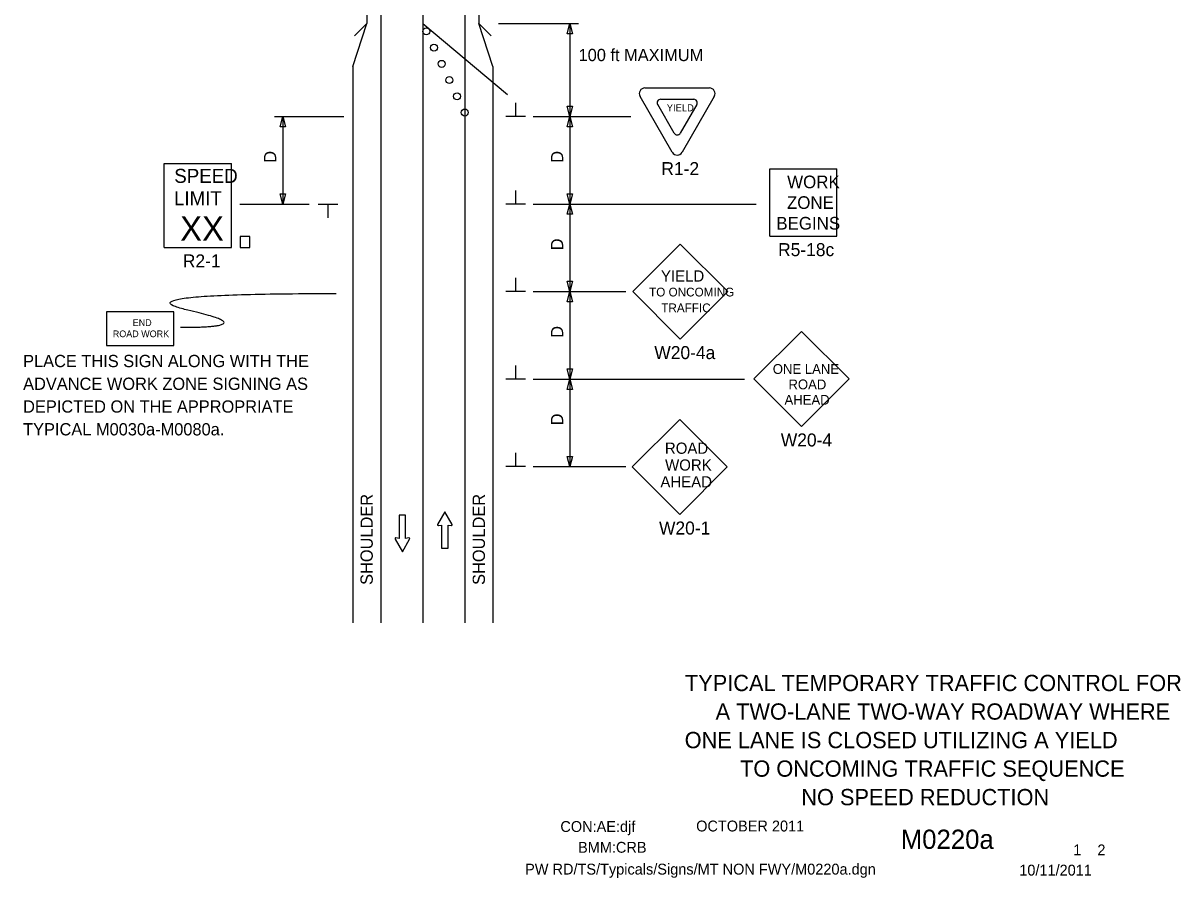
# Model space of a CAD drawing. Extents: x 16784 to 18475, y 7218 to 8259.
# Drawn here: x 16784 to 17445, y 7218 to 7706 of the extents above; entities that cross this region are included whole.
import ezdxf

# ---------------------------------------------------------------- set-up
doc = ezdxf.new("R2010")
doc.units = 0
for name, color, linetype in [('BORDER', 7, 'Continuous'), ('BORDER_SIGNAL_WO', 7, 'Continuous'), ('MT_SCRATCH_LEVEL_E', 7, 'Continuous'), ('PAVT_EDGE_EX', 7, 'Continuous'), ('TRAFFIC_SIGNS_PR', 7, 'Continuous'), ('TYPICAL_TEXT_DIMEN_PR', 7, 'Continuous')]:
    doc.layers.add(name, color=color, linetype=linetype)

msp = doc.modelspace()

# ---------------------------------------------------------------- linework, layer by layer
at = {"layer": 'MT_SCRATCH_LEVEL_E'}
for p, q in [((17002.27, 7425.26), (16998.52, 7425.26)), ((16998.52, 7425.26), (16998.52, 7412.01)), ((17002.27, 7425.26), (16998.52, 7425.26)), ((16998.52, 7425.26), (16998.52, 7412.01)), ((17002.27, 7412.01), (17002.27, 7425.26)), ((17002.27, 7412.01), (17002.27, 7425.26)), ((17024.66, 7427.22), (17020.55, 7419.98)), ((17024.66, 7427.22), (17020.55, 7419.98)), ((17028.81, 7419.98), (17024.66, 7427.22)), ((17028.81, 7419.98), (17024.66, 7427.22)), ((17021.03, 7419.29), (17022.81, 7419.61)), ((17021.03, 7419.29), (17022.81, 7419.61)), ((17022.81, 7419.61), (17022.81, 7406.35)), ((17022.81, 7419.61), (17022.81, 7406.35)), ((17026.55, 7406.35), (17026.55, 7419.61)), ((17026.55, 7419.61), (17028.33, 7419.29)), ((17026.55, 7406.35), (17026.55, 7419.61)), ((17026.55, 7419.61), (17028.33, 7419.29)), ((16996.27, 7411.64), (17000.41, 7404.4)), ((16996.27, 7411.64), (17000.41, 7404.4)), ((16998.52, 7412.01), (16996.75, 7412.32)), ((16998.52, 7412.01), (16996.75, 7412.32)), ((17000.41, 7404.4), (17004.53, 7411.64)), ((17000.41, 7404.4), (17004.53, 7411.64)), ((17004.04, 7412.32), (17002.27, 7412.01)), ((17004.04, 7412.32), (17002.27, 7412.01)), ((17022.81, 7406.35), (17026.55, 7406.35)), ((17022.81, 7406.35), (17026.55, 7406.35))]:
    msp.add_line(p, q, dxfattribs=at)
for centre, start, end in [((17020.95, 7419.75), 150.42484, 279.96381), ((17020.95, 7419.75), 150.42484, 279.96381), ((17028.4, 7419.75), 260.03619, 29.77312), ((17028.4, 7419.75), 260.03619, 29.77312), ((16996.68, 7411.86), 80.03619, 209.77312), ((16996.68, 7411.86), 80.03619, 209.77312), ((17004.12, 7411.86), 330.42484, 99.96381), ((17004.12, 7411.86), 330.42484, 99.96381)]:
    msp.add_arc(centre, 0.463, start, end, dxfattribs=at)
at = {"layer": 'PAVT_EDGE_EX'}
for p, q in [((16988.07, 8185.68), (16988.07, 7363.75)), ((17012.07, 8185.68), (17012.07, 7363.75)), ((17036.07, 8185.68), (17036.07, 7363.75)), ((16980.07, 7837.6), (16980.07, 7706.21)), ((17012.07, 7837.6), (17012.07, 7706.21)), ((17044.07, 7837.6), (17044.07, 7706.21)), ((16972.07, 7681.51), (16980.07, 7706.21)), ((16980.07, 7706.21), (16973, 7699.14)), ((17012.07, 7706.21), (17060.48, 7665.59)), ((17044.07, 7706.21), (17051.14, 7699.14)), ((17052.07, 7681.51), (17044.07, 7706.21)), ((16972.07, 7681.51), (16972.07, 7363.75)), ((17052.07, 7681.51), (17052.07, 7363.75))]:
    msp.add_line(p, q, dxfattribs=at)
for points in [[(17012.07, 7685.68), (17012.07, 7660.68)], [(17012.07, 7585.68), (17012.07, 7560.68)], [(17012.07, 7485.68), (17012.07, 7460.68)], [(17012.07, 7385.68), (17012.07, 7363.75)]]:
    msp.add_lwpolyline(points, dxfattribs=at)
at = {"layer": 'TRAFFIC_SIGNS_PR'}
for p, q in [((17138.98, 7669.34), (17175.9, 7669.34)), ((17154.67, 7632.57), (17136.21, 7664.54)), ((17148.03, 7662.87), (17166.93, 7662.87)), ((17178.67, 7664.54), (17160.21, 7632.57)), ((17155.75, 7643.5), (17146.3, 7659.87)), ((17168.66, 7659.87), (17159.21, 7643.5)), ((16864.3, 7626.26), (16902.7, 7626.26)), ((16864.3, 7578.26), (16864.3, 7626.26)), ((16902.7, 7578.26), (16902.7, 7626.26)), ((17210.31, 7584.69), (17210.31, 7623.09)), ((17210.31, 7623.09), (17248.71, 7623.09)), ((17248.71, 7584.69), (17248.71, 7623.09)), ((17210.31, 7584.69), (17248.71, 7584.69)), ((16864.3, 7578.26), (16902.7, 7578.26)), ((17159.25, 7580.19), (17132.09, 7553.04)), ((17186.4, 7553.04), (17159.25, 7580.19)), ((17132.09, 7553.04), (17159.25, 7525.88)), ((17159.25, 7525.88), (17186.4, 7553.04)), ((17228.49, 7530.26), (17201.34, 7503.11)), ((17255.64, 7503.11), (17228.49, 7530.26)), ((17201.34, 7503.11), (17228.49, 7475.96)), ((17228.49, 7475.96), (17255.64, 7503.11)), ((17158.9, 7479.95), (17131.74, 7452.8)), ((17186.05, 7452.8), (17158.9, 7479.95)), ((17131.74, 7452.8), (17158.9, 7425.65)), ((17158.9, 7425.65), (17186.05, 7452.8))]:
    msp.add_line(p, q, dxfattribs=at)
for points in [[(16907.71, 7578.26), (16913.31, 7578.26), (16913.31, 7584.43), (16907.71, 7584.43)], [(16831.33, 7522.23), (16869.73, 7522.23), (16869.73, 7541.43), (16831.33, 7541.43)]]:
    msp.add_lwpolyline(points, close=True, dxfattribs=at)
for centre in [(17014.07, 7701.63), (17018.47, 7692.37), (17022.87, 7683.1), (17027.27, 7673.84), (17031.67, 7664.57), (17036.07, 7655.31)]:
    msp.add_circle(centre, 2, dxfattribs=at)
for centre, radius, start, end in [((17138.98, 7666.14), 3.2, 90, 209.99924), ((17175.9, 7666.14), 3.2, 330.11476, 90), ((17133.44, 7662.94), 3.2, 29.99562, 29.99924), ((17148.03, 7660.87), 2, 90, 210.00073), ((17166.93, 7660.87), 2, 329.99927, 90), ((17157.48, 7644.5), 2, 210.00073, 329.99927), ((17157.44, 7634.17), 3.2, 209.99562, 211.51401), ((17157.44, 7634.17), 3.2, 211.51401, 330.00085), ((17162.98, 7630.97), 3.2, 149.99998, 150.00086)]:
    msp.add_arc(centre, radius, start, end, dxfattribs=at)
msp.add_open_spline([(16873.64, 7532.59), (16920.88, 7532.59), (16835.86, 7551.93), (16962.53, 7551.93)], degree=2, dxfattribs=at)
at = {"layer": 'TYPICAL_TEXT_DIMEN_PR'}
for p, q in [((17055.37, 7706.21), (17101.07, 7706.21)), ((17094.5, 7700.35), (17096.07, 7706.21)), ((17096.07, 7706.21), (17096.07, 7653.01)), ((17096.07, 7706.21), (17097.64, 7700.35)), ((17096.07, 7700.35), (17094.5, 7700.35)), ((17097.64, 7700.35), (17096.07, 7700.35)), ((17065.19, 7653.01), (17065.19, 7660.8)), ((17096.07, 7653.01), (17094.5, 7658.88)), ((17094.5, 7658.88), (17096.07, 7658.88)), ((17096.07, 7658.88), (17097.64, 7658.88)), ((17097.64, 7658.88), (17096.07, 7653.01)), ((16927.3, 7653.01), (16967.03, 7653.01)), ((16930.5, 7647.15), (16932.07, 7653.01)), ((16932.07, 7653.01), (16932.07, 7603.01)), ((16932.07, 7653.01), (16933.64, 7647.15)), ((17070.82, 7653.01), (17059.57, 7653.01)), ((17075.07, 7653.01), (17131.03, 7653.01)), ((17094.5, 7647.15), (17096.07, 7653.01)), ((17096.07, 7653.01), (17096.07, 7603.01)), ((17096.07, 7653.01), (17097.64, 7647.15)), ((16932.07, 7647.15), (16930.5, 7647.15)), ((16933.64, 7647.15), (16932.07, 7647.15)), ((17096.07, 7647.15), (17094.5, 7647.15)), ((17097.64, 7647.15), (17096.07, 7647.15)), ((16932.07, 7603.01), (16930.5, 7608.88)), ((16930.5, 7608.88), (16932.07, 7608.88)), ((16932.07, 7608.88), (16933.64, 7608.88)), ((16933.64, 7608.88), (16932.07, 7603.01)), ((17065.19, 7603.01), (17065.19, 7610.8)), ((17096.07, 7603.01), (17094.5, 7608.88)), ((17094.5, 7608.88), (17096.07, 7608.88)), ((17096.07, 7608.88), (17097.64, 7608.88)), ((17097.64, 7608.88), (17096.07, 7603.01)), ((16907.47, 7603.01), (16947.14, 7603.01)), ((16952.2, 7603.01), (16963.45, 7603.01)), ((16957.82, 7603.01), (16957.82, 7595.23)), ((17070.82, 7603.01), (17059.57, 7603.01)), ((17075.07, 7603.01), (17202.6, 7603.01)), ((17094.5, 7597.15), (17096.07, 7603.01)), ((17094.5, 7597.15), (17096.07, 7603.01)), ((17096.07, 7603.01), (17096.07, 7553.01)), ((17096.07, 7603.01), (17097.64, 7597.15)), ((17096.07, 7603.01), (17097.64, 7597.15)), ((17096.07, 7597.15), (17094.5, 7597.15)), ((17096.07, 7597.15), (17094.5, 7597.15)), ((17097.64, 7597.15), (17096.07, 7597.15)), ((17097.64, 7597.15), (17096.07, 7597.15)), ((17065.19, 7553.01), (17065.19, 7560.8)), ((17096.07, 7553.01), (17094.5, 7558.88)), ((17094.5, 7558.88), (17096.07, 7558.88)), ((17096.07, 7553.01), (17094.5, 7558.88)), ((17094.5, 7558.88), (17096.07, 7558.88)), ((17096.07, 7558.88), (17097.64, 7558.88)), ((17097.64, 7558.88), (17096.07, 7553.01)), ((17096.07, 7558.88), (17097.64, 7558.88)), ((17097.64, 7558.88), (17096.07, 7553.01)), ((17070.82, 7553.01), (17059.57, 7553.01)), ((17075.07, 7553.01), (17128.13, 7553.01)), ((17094.5, 7547.15), (17096.07, 7553.01)), ((17094.5, 7547.15), (17096.07, 7553.01)), ((17096.07, 7553.01), (17096.07, 7503.01)), ((17096.07, 7553.01), (17097.64, 7547.15)), ((17096.07, 7553.01), (17097.64, 7547.15)), ((17096.07, 7547.15), (17094.5, 7547.15)), ((17096.07, 7547.15), (17094.5, 7547.15)), ((17097.64, 7547.15), (17096.07, 7547.15)), ((17097.64, 7547.15), (17096.07, 7547.15)), ((17065.19, 7503.01), (17065.19, 7510.8)), ((17096.07, 7503.01), (17094.5, 7508.88)), ((17094.5, 7508.88), (17096.07, 7508.88)), ((17096.07, 7508.88), (17097.64, 7508.88)), ((17097.64, 7508.88), (17096.07, 7503.01)), ((17070.82, 7503.01), (17059.57, 7503.01)), ((17075.07, 7503.01), (17196, 7503.01)), ((17094.5, 7497.15), (17096.07, 7503.01)), ((17096.07, 7503.01), (17096.07, 7453.01)), ((17096.07, 7503.01), (17097.64, 7497.15)), ((17096.07, 7497.15), (17094.5, 7497.15)), ((17097.64, 7497.15), (17096.07, 7497.15)), ((17065.19, 7453.01), (17065.19, 7460.8)), ((17096.07, 7453.01), (17094.5, 7458.88)), ((17094.5, 7458.88), (17096.07, 7458.88)), ((17096.07, 7458.88), (17097.64, 7458.88)), ((17097.64, 7458.88), (17096.07, 7453.01)), ((17070.82, 7453.01), (17059.57, 7453.01)), ((17075.07, 7453.01), (17128.13, 7453.01))]:
    msp.add_line(p, q, dxfattribs=at)

# ---------------------------------------------------------------- texts
at = {"layer": 'BORDER'}
for s, p in [('TYPICAL TEMPORARY TRAFFIC CONTROL FOR', (17161.87, 7324.76)), ('A TWO-LANE TWO-WAY ROADWAY WHERE', (17179.39, 7308.46)), ('ONE LANE IS CLOSED UTILIZING A YIELD ', (17161.74, 7292.16)), ('TO ONCOMING TRAFFIC SEQUENCE', (17193.39, 7275.86)), ('NO SPEED REDUCTION', (17228.37, 7259.56))]:
    msp.add_text(s, height=9.3, dxfattribs=at).set_placement(p)
at = {"layer": 'BORDER_SIGNAL_WO'}
for s, height, p in [('CON:AE:djf', 6.2, (17090.69, 7244.31)), ('    OCTOBER 2011    ', 6.2, (17159.08, 7244.59)), ('    M0220a    ', 11, (17268.86, 7234.63)), ('BMM:CRB   ', 6.2, (17100.81, 7232.42)), (' 1    2 ', 6.2, (17381.45, 7230.95)), ('PW RD/TS/Typicals/Signs/MT NON FWY/M0220a.dgn     ', 6.2, (17070.55, 7219.96)), ('10/11/2011    ', 6.2, (17352.93, 7219.38))]:
    msp.add_text(s, height=height, dxfattribs=at).set_placement(p)
at = {"layer": 'TRAFFIC_SIGNS_PR'}
for s, height, p in [('YIELD', 4, (17151.51, 7656.01)), ('SPEED', 8, (16870.06, 7615.12)), ('R1-2', 7.44, (17148.43, 7619.53)), ('WORK', 7.217, (17220.31, 7612.06)), ('LIMIT', 8, (16869.9, 7602.32)), ('ZONE', 7.217, (17220.19, 7600.25)), ('XX', 14.031, (16873.41, 7582.01)), ('BEGINS', 7.217, (17214.12, 7588.44)), ('R5-18c', 7.44, (17215.12, 7573.25)), ('R2-1', 7.44, (16874.97, 7566.82)), ('YIELD', 6.4, (17148.19, 7558.71)), ('TO ONCOMING', 5, (17141.39, 7550.23)), ('TRAFFIC', 5, (17148.36, 7541.23)), ('END', 3.831, (16846.33, 7533.36)), ('ROAD WORK', 3.831, (16834.94, 7526.97)), ('PLACE THIS SIGN ALONG WITH THE', 7, (16783.68, 7509.85)), ('W20-4a', 7.44, (17144.39, 7514.44)), ('ONE LANE', 5.6, (17212.08, 7505.98)), ('ADVANCE WORK ZONE SIGNING AS', 7, (16783.68, 7496.85)), ('ROAD', 5.6, (17221.03, 7497.18)), ('DEPICTED ON THE APPROPRIATE', 7, (16783.68, 7483.85)), ('AHEAD', 5.6, (17218.78, 7488.38)), ('TYPICAL M0030a-M0080a.', 7, (16783.68, 7470.85)), ('W20-4', 7.44, (17216.67, 7464.52)), ('ROAD', 6.4, (17150.44, 7460.34)), ('WORK', 6.4, (17150.55, 7450.74)), ('AHEAD', 6.4, (17147.86, 7441.14)), ('W20-1', 7.44, (17147.07, 7414.21))]:
    msp.add_text(s, height=height, dxfattribs=at).set_placement(p)
at = {"layer": 'TYPICAL_TEXT_DIMEN_PR'}
msp.add_text('100 ft MAXIMUM', height=7, dxfattribs=at).set_placement((17101.11, 7684.68))
for s, p in [('D', (16928.32, 7626.59)), ('D', (17092.32, 7626.59)), ('D', (17092.32, 7576.59)), ('D', (17092.32, 7526.59)), ('D', (17092.32, 7476.59)), ('SHOULDER', (16983.49, 7385.43)), ('SHOULDER', (17047.6, 7385.43))]:
    msp.add_text(s, height=7, rotation=90, dxfattribs=at).set_placement(p)

doc.saveas('drawing.dxf')
